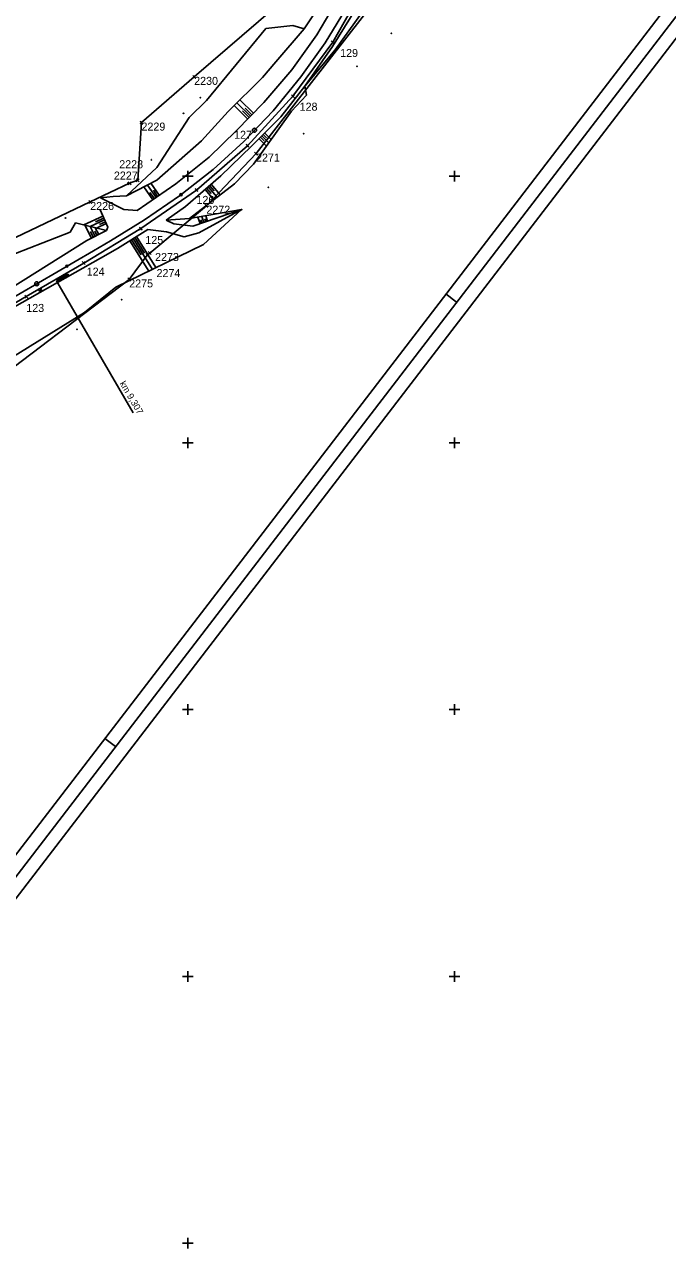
# Model space of a CAD drawing. Extents: x -866402 to -860377, y -1041908 to -1038598.
# Drawn here: x -862661.2 to -862420.2, y -1040102 to -1039643.2 of the extents above; entities that cross this region are included whole.
import ezdxf

# ---------------------------------------------------------------- set-up
doc = ezdxf.new("R2010")
doc.units = 0
for name, color, linetype in [('PS 02 trasa', 7, 'Continuous'), ('SZDC', 7, 'Continuous'), ('Vrstva 1', 7, 'Continuous'), ('Vrstva 48', 7, 'Continuous'), ('Vrstva 49', 7, 'Continuous'), ('Vrstva 5', 7, 'Continuous'), ('Vrstva 60', 7, 'Continuous'), ('Vrstva 7', 7, 'Continuous'), ('Vrstva 9', 7, 'Continuous')]:
    doc.layers.add(name, color=color, linetype=linetype)

msp = doc.modelspace()

# ---------------------------------------------------------------- linework, layer by layer
at = {"layer": 'PS 02 trasa'}
msp.add_lwpolyline([(-862682.23, -1039757.8), (-862660.52, -1039745.14), (-862639, -1039732.58), (-862617.58, -1039719.69), (-862596.73, -1039705.22), (-862577.61, -1039688.61), (-862560.6, -1039670.06), (-862545.68, -1039649.8), (-862530.76, -1039623.44)], dxfattribs=at)
at = {"layer": 'SZDC'}
for points in [[(-863165.8, -1039964.66), (-863118.75, -1039967.2), (-863083.63, -1039964.52), (-863052.89, -1039954), (-863012.74, -1039930), (-862976.58, -1039912.97), (-862937.72, -1039894.02), (-862895.01, -1039875.47), (-862835.6, -1039838.65), (-862807.35, -1039814.81), (-862775.54, -1039789.79), (-862724.48, -1039769.5), (-862710.01, -1039753.11), (-862692.04, -1039737.42), (-862692.5, -1039729.46), (-862678.31, -1039732.26), (-862673.01, -1039726.98), (-862636.56, -1039709.7), (-862621.8, -1039702.7), (-862618.74, -1039701.53), (-862617.34, -1039679.93), (-862597.59, -1039662.79), (-862567.2, -1039636.61)], [(-862533.82, -1039639.47), (-862574.41, -1039691.56), (-862593.02, -1039711.09), (-862614.27, -1039728.82), (-862615.17, -1039729.57), (-862621.94, -1039738.72), (-862678.71, -1039781.76)]]:
    msp.add_lwpolyline(points, dxfattribs=at)
at = {"layer": 'Vrstva 1'}
for p, q in [((-862503.25, -1039744.17), (-862499.29, -1039747.21)), ((-862631.08, -1039910.78), (-862627.12, -1039913.82))]:
    msp.add_line(p, q, dxfattribs=at)
for points in [[(-862750.99, -1040083.46), (-861983.98, -1039083.83), (-862219.6, -1038903.04), (-862986.61, -1039902.67)], [(-862979.6, -1039901.75), (-862218.68, -1038910.05), (-861990.99, -1039084.75), (-862751.92, -1040076.45)], [(-862752.84, -1040069.45), (-862122.79, -1039248.31), (-862342.55, -1039079.69), (-862972.6, -1039900.83)], [(-862972.6, -1039900.83), (-862342.55, -1039079.69), (-862122.79, -1039248.31), (-862752.84, -1040069.45)]]:
    msp.add_lwpolyline(points, close=True, dxfattribs=at)
for points in [[(-862635.33, -1039727.96), (-862628.97, -1039724.2), (-862616.24, -1039716.36), (-862603.07, -1039707.37), (-862590.53, -1039697.47), (-862579.03, -1039687), (-862568.05, -1039675.52), (-862557.58, -1039662.82), (-862548.5, -1039650.05), (-862539.56, -1039635.32), (-862531.65, -1039619.63), (-862525.21, -1039604.06), (-862519.84, -1039587.79), (-862515.9, -1039571.79), (-862513.1, -1039555.19), (-862511.49, -1039538.76), (-862510.91, -1039522.22), (-862511.11, -1039505.52), (-862511.19, -1039502.39), (-862511.5, -1039492.41)], [(-862981.15, -1039929.12), (-862954.67, -1039913.73), (-862917.53, -1039892.09), (-862879, -1039869.71), (-862841.95, -1039848.16), (-862805.68, -1039827.06), (-862769.2, -1039805.87), (-862695.36, -1039762.88), (-862669.67, -1039747.95), (-862635.33, -1039727.96)]]:
    msp.add_lwpolyline(points, dxfattribs=at)
for centre in [(-862602.51, -1039706.93), (-862645.31, -1039733.77)]:
    msp.add_circle(centre, 0.4, dxfattribs=at)
at = {"layer": 'Vrstva 48'}
for p, q in [((-862577.51, -1039678.6), (-862582.62, -1039673.56)), ((-862576.46, -1039677.53), (-862581.56, -1039672.51)), ((-862575.4, -1039676.46), (-862580.49, -1039671.46)), ((-862575.93, -1039677), (-862578.48, -1039674.49)), ((-862576.98, -1039678.07), (-862579.54, -1039675.55)), ((-862571.17, -1039683.85), (-862568.74, -1039686.28)), ((-862573.29, -1039685.97), (-862570.51, -1039688.74)), ((-862572.76, -1039685.44), (-862571.42, -1039686.78)), ((-862572.23, -1039684.91), (-862569.63, -1039687.51)), ((-862571.7, -1039684.38), (-862570.44, -1039685.64)), ((-862613.14, -1039708.9), (-862616.48, -1039704.04)), ((-862611.9, -1039708.05), (-862615.14, -1039703.35)), ((-862612.52, -1039708.47), (-862614.16, -1039706.08)), ((-862610.67, -1039707.2), (-862613.79, -1039702.65)), ((-862611.29, -1039707.62), (-862612.87, -1039705.31)), ((-862593.51, -1039705.03), (-862590.19, -1039708.85)), ((-862592.94, -1039704.54), (-862591.27, -1039706.46)), ((-862592.38, -1039704.05), (-862589, -1039707.93)), ((-862591.81, -1039703.55), (-862590.11, -1039705.51)), ((-862591.24, -1039703.06), (-862587.81, -1039707.02)), ((-862631.8, -1039715.06), (-862638.94, -1039718.3)), ((-862631.48, -1039715.74), (-862634.62, -1039717.16)), ((-862595.39, -1039717.81), (-862596.22, -1039715.37)), ((-862593.97, -1039717.33), (-862594.72, -1039715.11)), ((-862593.26, -1039717.09), (-862593.62, -1039716.04)), ((-862592.55, -1039716.85), (-862593.23, -1039714.85)), ((-862636.07, -1039723.26), (-862638.55, -1039718.4)), ((-862634.73, -1039722.58), (-862636.62, -1039718.86)), ((-862631.18, -1039716.42), (-862636.58, -1039718.87)), ((-862635.4, -1039722.92), (-862636.49, -1039720.78)), ((-862634.06, -1039722.24), (-862634.86, -1039720.67)), ((-862633.39, -1039721.9), (-862634.7, -1039719.33)), ((-862630.56, -1039717.79), (-862634.22, -1039719.45)), ((-862630.86, -1039717.1), (-862633.13, -1039718.13)), ((-862594.68, -1039717.57), (-862595.08, -1039716.41)), ((-862621.7, -1039724.22), (-862614.63, -1039735.61)), ((-862621.06, -1039723.83), (-862617.51, -1039729.56)), ((-862620.43, -1039723.43), (-862613.27, -1039734.95)), ((-862619.79, -1039723.04), (-862616.19, -1039728.83)), ((-862619.15, -1039722.64), (-862611.92, -1039734.29))]:
    msp.add_line(p, q, dxfattribs=at)
at = {"layer": 'Vrstva 49'}
for p, q in [((-862536.81, -1039636.89), (-862545.8, -1039651.38)), ((-862544.76, -1039652.71), (-862534.46, -1039638.36)), ((-862592.92, -1039671.6), (-862570.68, -1039644.67)), ((-862560.65, -1039643.5), (-862570.68, -1039644.67)), ((-862556.4, -1039644.81), (-862560.65, -1039643.5)), ((-862523.93, -1039646.26), (-862523.57, -1039646.61)), ((-862523.93, -1039646.61), (-862523.57, -1039646.26)), ((-862545.8, -1039651.38), (-862556.11, -1039666.29)), ((-862556.11, -1039666.29), (-862544.76, -1039652.71)), ((-862536.71, -1039658.71), (-862536.36, -1039659.06)), ((-862536.71, -1039659.06), (-862536.36, -1039658.71)), ((-862595.42, -1039670.36), (-862595.07, -1039670.72)), ((-862595.42, -1039670.72), (-862595.07, -1039670.36)), ((-862565.06, -1039677.73), (-862556.11, -1039666.29)), ((-862601.78, -1039676.3), (-862601.42, -1039676.66)), ((-862601.78, -1039676.66), (-862601.42, -1039676.3)), ((-862556.69, -1039683.96), (-862556.34, -1039684.32)), ((-862556.69, -1039684.32), (-862556.34, -1039683.96)), ((-862613.84, -1039693.72), (-862613.49, -1039694.07)), ((-862613.84, -1039694.07), (-862613.49, -1039693.72)), ((-862622.99, -1039707.4), (-862611.63, -1039701.54)), ((-862622.54, -1039702.42), (-862622.19, -1039702.77)), ((-862622.54, -1039702.77), (-862622.19, -1039702.42)), ((-862600.85, -1039711.4), (-862587.61, -1039699.91)), ((-862618.92, -1039712.87), (-862604.5, -1039702.95)), ((-862599.36, -1039715.91), (-862582.53, -1039702.95)), ((-862569.93, -1039704.02), (-862569.58, -1039704.37)), ((-862569.93, -1039704.37), (-862569.58, -1039704.02)), ((-862608.13, -1039716.5), (-862600.85, -1039711.4)), ((-862645.99, -1039715.57), (-862645.64, -1039715.92)), ((-862645.99, -1039715.92), (-862645.64, -1039715.57)), ((-862608.13, -1039716.5), (-862599.36, -1039715.91)), ((-862599.36, -1039715.91), (-862579.8, -1039712.53)), ((-862579.98, -1039712.35), (-862579.63, -1039712.71)), ((-862579.98, -1039712.71), (-862579.63, -1039712.35)), ((-862644.05, -1039721.01), (-862642.03, -1039717.55)), ((-862642.03, -1039717.55), (-862630.4, -1039720.38)), ((-862637.82, -1039724.16), (-862630.4, -1039720.38)), ((-862608.13, -1039716.5), (-862605.19, -1039717.9)), ((-862671.53, -1039745.2), (-862637.82, -1039724.16)), ((-862638.73, -1039751.17), (-862626.91, -1039741.6)), ((-862624.94, -1039746.09), (-862624.59, -1039746.44)), ((-862624.94, -1039746.44), (-862624.59, -1039746.09)), ((-862697.78, -1039787.67), (-862638.73, -1039751.17)), ((-862641.71, -1039757.25), (-862641.36, -1039757.6)), ((-862641.71, -1039757.6), (-862641.36, -1039757.25))]:
    msp.add_line(p, q, dxfattribs=at)
for points in [[(-862548.99, -1039633.54), (-862556.4, -1039644.81), (-862566.94, -1039657.21), (-862571.97, -1039663.08), (-862584.9, -1039675.8), (-862594.88, -1039686.8), (-862611.63, -1039701.54)], [(-862604.5, -1039702.95), (-862591.93, -1039692.93), (-862581.86, -1039683.02), (-862571.45, -1039672.45), (-862560.94, -1039660.21), (-862551.66, -1039647.01), (-862543.46, -1039633.2)], [(-862556.11, -1039666.29), (-862555.55, -1039669.69), (-862561.11, -1039675.67)], [(-862592.92, -1039671.6), (-862599.46, -1039678.08), (-862611.54, -1039696.8), (-862622.99, -1039707.4)], [(-862565.06, -1039677.73), (-862576.13, -1039688.82), (-862587.61, -1039699.91)], [(-862582.53, -1039702.95), (-862575.39, -1039695.53), (-862561.11, -1039675.67)], [(-862632.75, -1039708.16), (-862627.96, -1039707.68), (-862622.99, -1039707.4)], [(-862618.92, -1039712.87), (-862623.96, -1039712.49), (-862632.75, -1039708.16)], [(-862630.4, -1039720.38), (-862629.97, -1039719.08), (-862632.86, -1039712.7)], [(-862626.91, -1039741.6), (-862594.07, -1039725.59), (-862579.8, -1039712.53)], [(-862614.96, -1039720.04), (-862607.98, -1039720.88), (-862601.4, -1039722.74), (-862595.84, -1039721.3), (-862579.8, -1039712.53)], [(-862605.19, -1039717.9), (-862598.06, -1039718.71), (-862579.8, -1039712.53)], [(-862632.66, -1039730.7), (-862626.29, -1039727.07), (-862614.96, -1039720.04)], [(-862708.32, -1039750.9), (-862698.27, -1039743.02), (-862690.34, -1039738.95), (-862644.05, -1039721.01)], [(-862632.66, -1039730.7), (-862668.7, -1039751.14), (-862688.54, -1039763.22)]]:
    msp.add_lwpolyline(points, dxfattribs=at)
at = {"layer": 'Vrstva 5'}
for p, q in [((-862602, -1039700), (-862598, -1039700)), ((-862600, -1039698), (-862600, -1039702)), ((-862502, -1039700), (-862498, -1039700)), ((-862500, -1039698), (-862500, -1039702)), ((-862600, -1039798), (-862600, -1039802)), ((-862500, -1039798), (-862500, -1039802)), ((-862602, -1039800), (-862598, -1039800)), ((-862502, -1039800), (-862498, -1039800)), ((-862600, -1039898), (-862600, -1039902)), ((-862500, -1039898), (-862500, -1039902)), ((-862602, -1039900), (-862598, -1039900)), ((-862502, -1039900), (-862498, -1039900)), ((-862602, -1040000), (-862598, -1040000)), ((-862600, -1039998), (-862600, -1040002)), ((-862502, -1040000), (-862498, -1040000)), ((-862500, -1039998), (-862500, -1040002)), ((-862602, -1040100), (-862598, -1040100)), ((-862600, -1040098), (-862600, -1040102))]:
    msp.add_line(p, q, dxfattribs=at)
at = {"layer": 'Vrstva 60'}
for p, q in [((-862545.22, -1039650.25), (-862546.22, -1039649.25)), ((-862545.22, -1039649.35), (-862546.22, -1039650.35)), ((-862546.12, -1039650.25), (-862545.12, -1039649.25)), ((-862546.12, -1039649.35), (-862545.12, -1039650.35)), ((-862545.68, -1039649.8), (-862545.68, -1039649.8)), ((-862597.14, -1039663.24), (-862598.14, -1039662.24)), ((-862597.14, -1039662.34), (-862598.14, -1039663.34)), ((-862598.04, -1039663.24), (-862597.04, -1039662.24)), ((-862598.04, -1039662.34), (-862597.04, -1039663.34)), ((-862597.59, -1039662.79), (-862597.59, -1039662.79)), ((-862560.15, -1039670.51), (-862561.15, -1039669.51)), ((-862560.15, -1039669.61), (-862561.15, -1039670.61)), ((-862561.05, -1039670.51), (-862560.05, -1039669.51)), ((-862561.05, -1039669.61), (-862560.05, -1039670.61)), ((-862560.6, -1039670.06), (-862560.6, -1039670.06)), ((-862616.89, -1039680.38), (-862617.89, -1039679.38)), ((-862616.89, -1039679.48), (-862617.89, -1039680.48)), ((-862617.79, -1039680.38), (-862616.79, -1039679.38)), ((-862617.79, -1039679.48), (-862616.79, -1039680.48)), ((-862617.34, -1039679.93), (-862617.34, -1039679.93)), ((-862577.17, -1039689.06), (-862578.17, -1039688.06)), ((-862577.17, -1039688.16), (-862578.17, -1039689.16)), ((-862578.07, -1039689.06), (-862577.07, -1039688.06)), ((-862578.07, -1039688.16), (-862577.07, -1039689.16)), ((-862577.61, -1039688.61), (-862577.61, -1039688.61)), ((-862573.96, -1039692.01), (-862574.96, -1039691.01)), ((-862573.96, -1039691.11), (-862574.96, -1039692.11)), ((-862574.85, -1039692.01), (-862573.85, -1039691.01)), ((-862574.85, -1039691.11), (-862573.85, -1039692.11)), ((-862574.41, -1039691.56), (-862574.41, -1039691.56)), ((-862621.35, -1039703.15), (-862622.35, -1039702.15)), ((-862621.35, -1039702.25), (-862622.35, -1039703.25)), ((-862622.25, -1039703.15), (-862621.25, -1039702.15)), ((-862622.25, -1039702.25), (-862621.25, -1039703.25)), ((-862618.29, -1039701.98), (-862619.29, -1039700.98)), ((-862618.29, -1039701.08), (-862619.29, -1039702.08)), ((-862619.19, -1039701.98), (-862618.19, -1039700.98)), ((-862619.19, -1039701.08), (-862618.19, -1039702.08)), ((-862618.74, -1039701.53), (-862618.74, -1039701.53)), ((-862621.8, -1039702.7), (-862621.8, -1039702.7)), ((-862596.28, -1039705.68), (-862597.28, -1039704.68)), ((-862596.28, -1039704.78), (-862597.28, -1039705.78)), ((-862597.18, -1039705.68), (-862596.18, -1039704.68)), ((-862597.18, -1039704.78), (-862596.18, -1039705.78)), ((-862596.73, -1039705.22), (-862596.73, -1039705.22)), ((-862636.11, -1039710.15), (-862637.11, -1039709.15)), ((-862636.11, -1039709.25), (-862637.11, -1039710.25)), ((-862637.01, -1039710.15), (-862636.01, -1039709.15)), ((-862637.01, -1039709.25), (-862636.01, -1039710.25)), ((-862636.56, -1039709.7), (-862636.56, -1039709.7)), ((-862592.57, -1039711.54), (-862593.57, -1039710.54)), ((-862592.57, -1039710.64), (-862593.57, -1039711.64)), ((-862593.47, -1039711.54), (-862592.47, -1039710.54)), ((-862593.47, -1039710.64), (-862592.47, -1039711.64)), ((-862593.02, -1039711.09), (-862593.02, -1039711.09)), ((-862617.13, -1039720.14), (-862618.13, -1039719.14)), ((-862617.13, -1039719.24), (-862618.13, -1039720.24)), ((-862618.03, -1039720.14), (-862617.03, -1039719.14)), ((-862618.03, -1039719.24), (-862617.03, -1039720.24)), ((-862617.58, -1039719.69), (-862617.58, -1039719.69)), ((-862614.72, -1039730.02), (-862615.72, -1039729.02)), ((-862614.72, -1039729.12), (-862615.72, -1039730.12)), ((-862615.62, -1039730.02), (-862614.62, -1039729.02)), ((-862615.62, -1039729.12), (-862614.62, -1039730.12)), ((-862615.17, -1039729.57), (-862615.17, -1039729.57)), ((-862613.82, -1039729.27), (-862614.82, -1039728.27)), ((-862613.82, -1039728.37), (-862614.82, -1039729.37)), ((-862614.72, -1039729.27), (-862613.72, -1039728.27)), ((-862614.72, -1039728.37), (-862613.72, -1039729.37)), ((-862614.27, -1039728.82), (-862614.27, -1039728.82)), ((-862638.55, -1039733.03), (-862639.55, -1039732.03)), ((-862638.55, -1039732.13), (-862639.55, -1039733.13)), ((-862639.45, -1039733.03), (-862638.45, -1039732.03)), ((-862639.45, -1039732.13), (-862638.45, -1039733.13)), ((-862639, -1039732.58), (-862639, -1039732.58)), ((-862621.49, -1039739.17), (-862622.49, -1039738.17)), ((-862621.49, -1039738.27), (-862622.49, -1039739.27)), ((-862622.39, -1039739.17), (-862621.39, -1039738.17)), ((-862622.39, -1039738.27), (-862621.39, -1039739.27)), ((-862621.94, -1039738.72), (-862621.94, -1039738.72)), ((-862660.07, -1039745.59), (-862661.07, -1039744.59)), ((-862660.07, -1039744.69), (-862661.07, -1039745.69)), ((-862660.97, -1039745.59), (-862659.97, -1039744.59)), ((-862660.97, -1039744.69), (-862659.97, -1039745.69)), ((-862660.52, -1039745.14), (-862660.52, -1039745.14))]:
    msp.add_line(p, q, dxfattribs=at)
at = {"layer": 'Vrstva 7'}
msp.add_line((-862655.35, -1039742.62), (-862655.25, -1039742.62), dxfattribs=at)
for centre, radius in [((-862574.99, -1039682.78), 0.75), ((-862656.62, -1039740.35), 0.75), ((-862655.3, -1039742.62), 0.5)]:
    msp.add_circle(centre, radius, dxfattribs=at)
at = {"layer": 'Vrstva 9'}
for p, q in [((-862644.91, -1039736.74), (-862649.23, -1039739.25)), ((-862649.23, -1039739.25), (-862648.93, -1039739.77)), ((-862648.93, -1039739.77), (-862644.61, -1039737.26)), ((-862644.61, -1039737.26), (-862644.91, -1039736.74)), ((-862649.08, -1039739.51), (-862620.52, -1039788.77)), ((-862648.93, -1039739.77), (-862648.63, -1039740.29))]:
    msp.add_line(p, q, dxfattribs=at)

# ---------------------------------------------------------------- texts
at = {"layer": 'Vrstva 60'}
for s, p in [('129', (-862542.88, -1039655.35)), ('2230', (-862597.59, -1039665.79)), ('128', (-862558.07, -1039675.48)), ('2229', (-862617.34, -1039682.93)), ('127', (-862582.64, -1039686.01)), ('2271', (-862574.41, -1039694.56)), ('2228', (-862625.67, -1039697.04)), ('2227', (-862627.68, -1039701.29)), ('2226', (-862636.56, -1039712.7)), ('126', (-862596.73, -1039710.41)), ('2272', (-862593.02, -1039714.09)), ('125', (-862615.9, -1039725.44)), ('2273', (-862612.25, -1039731.82)), ('124', (-862637.88, -1039737.31)), ('2275', (-862621.94, -1039741.72)), ('2274', (-862611.7, -1039737.84)), ('123', (-862660.52, -1039750.91))]:
    msp.add_text(s, height=3, dxfattribs=at).set_placement(p)
at = {"layer": 'Vrstva 9'}
msp.add_text('km 9,307', height=2.5, rotation=300.2101, dxfattribs=at).set_placement((-862625.62, -1039777.71))

doc.saveas('drawing.dxf')
